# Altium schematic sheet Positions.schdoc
size 368 x 210 mm
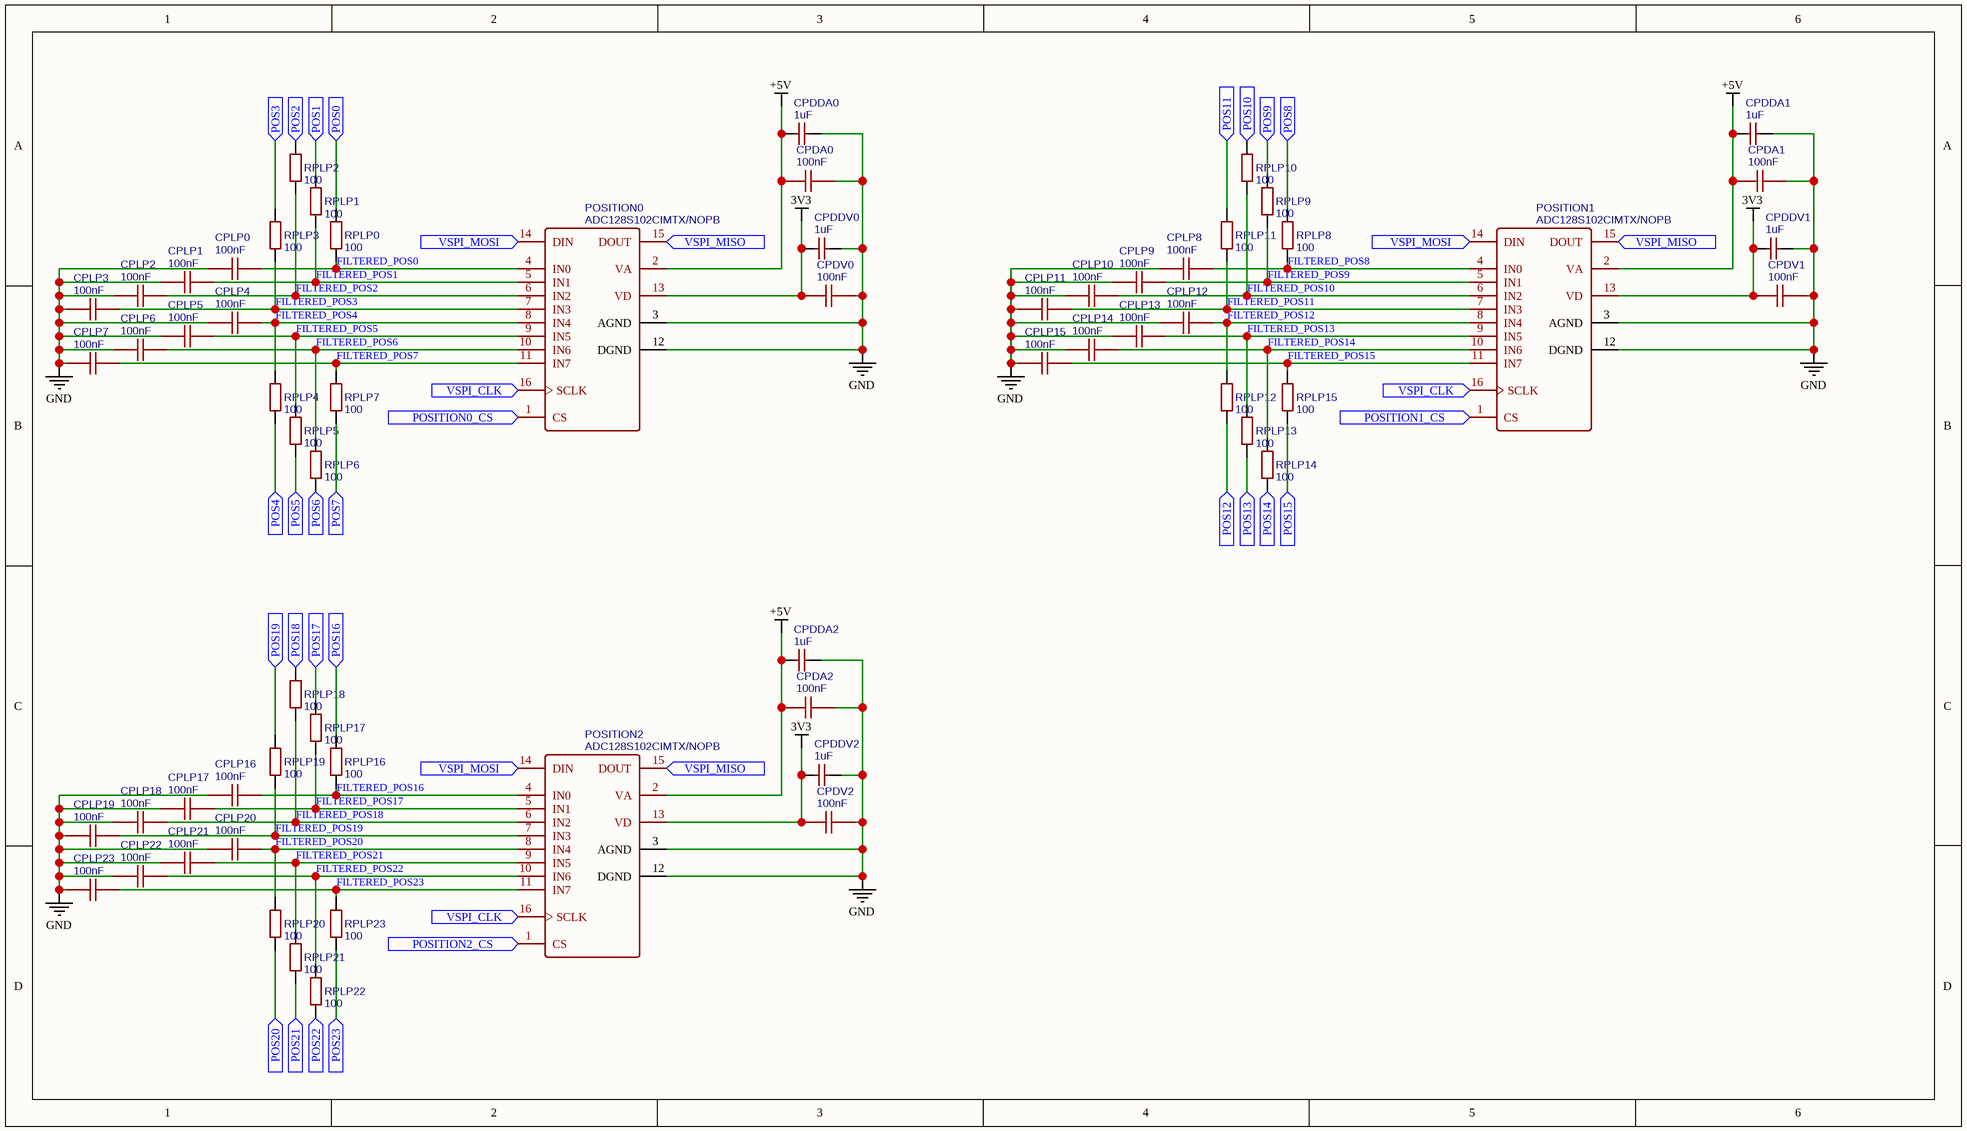
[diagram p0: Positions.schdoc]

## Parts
CPDA0  100nF  [0603]
CPDA1  100nF  [0603]
CPDA2  100nF  [0603]
CPDDA0  1uF  [0603]
CPDDA1  1uF  [0603]
CPDDA2  1uF  [0603]
CPDDV0  1uF  [0603]
CPDDV1  1uF  [0603]
CPDDV2  1uF  [0603]
CPDV0  100nF  [0603]
CPDV1  100nF  [0603]
CPDV2  100nF  [0603]
CPLP0  100nF  [0603]
CPLP1  100nF  [0603]
CPLP2  100nF  [0603]
CPLP3  100nF  [0603]
CPLP4  100nF  [0603]
CPLP5  100nF  [0603]
CPLP6  100nF  [0603]
CPLP7  100nF  [0603]
CPLP8  100nF  [0603]
CPLP9  100nF  [0603]
CPLP10  100nF  [0603]
CPLP11  100nF  [0603]
CPLP12  100nF  [0603]
CPLP13  100nF  [0603]
CPLP14  100nF  [0603]
CPLP15  100nF  [0603]
CPLP16  100nF  [0603]
CPLP17  100nF  [0603]
CPLP18  100nF  [0603]
CPLP19  100nF  [0603]
CPLP20  100nF  [0603]
CPLP21  100nF  [0603]
CPLP22  100nF  [0603]
CPLP23  100nF  [0603]
POSITION0  ADC128S102CIMTX/NOPB  [TSSOP-16-DOT-BOTTOM-RIGHT]
POSITION1  ADC128S102CIMTX/NOPB  [TSSOP-16-DOT-BOTTOM-RIGHT]
POSITION2  ADC128S102CIMTX/NOPB  [TSSOP-16-DOT-BOTTOM-RIGHT]
RPLP0  100  [0603]
RPLP1  100  [0603]
RPLP2  100  [0603]
RPLP3  100  [0603]
RPLP4  100  [0603]
RPLP5  100  [0603]
RPLP6  100  [0603]
RPLP7  100  [0603]
RPLP8  100  [0603]
RPLP9  100  [0603]
RPLP10  100  [0603]
RPLP11  100  [0603]
RPLP12  100  [0603]
RPLP13  100  [0603]
RPLP14  100  [0603]
RPLP15  100  [0603]
RPLP16  100  [0603]
RPLP17  100  [0603]
RPLP18  100  [0603]
RPLP19  100  [0603]
RPLP20  100  [0603]
RPLP21  100  [0603]
RPLP22  100  [0603]
RPLP23  100  [0603]

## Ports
POS0, POS1, POS2, POS3, POS4, POS5, POS6, POS7, POS8, POS9, POS10, POS11, POS12, POS13, POS14, POS15, POS16, POS17, POS18, POS19, POS20, POS21, POS22, POS23, POSITION0_CS, POSITION1_CS, POSITION2_CS, VSPI_CLK, VSPI_MISO, VSPI_MOSI

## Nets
3V3: CPDDV0.1 CPDDV1.1 CPDDV2.1 CPDV0.1 CPDV1.1 CPDV2.1 POSITION0.13(VD) POSITION1.13(VD) POSITION2.13(VD)
+5V: CPDA0.1 CPDA1.1 CPDA2.1 CPDDA0.1 CPDDA1.1 CPDDA2.1 POSITION0.2(VA) POSITION1.2(VA) POSITION2.2(VA)
GND: CPDA0.2 CPDA1.2 CPDA2.2 CPDDA0.2 CPDDA1.2 CPDDA2.2 CPDDV0.2 CPDDV1.2 CPDDV2.2 CPDV0.2 CPDV1.2 CPDV2.2 CPLP0.2 CPLP1.2 CPLP2.2 CPLP3.2 CPLP4.2 CPLP5.2 CPLP6.2 CPLP7.2 CPLP8.2 CPLP9.2 CPLP10.2 CPLP11.2 CPLP12.2 CPLP13.2 CPLP14.2 CPLP15.2 CPLP16.2 CPLP17.2 CPLP18.2 CPLP19.2 CPLP20.2 CPLP21.2 CPLP22.2 CPLP23.2 POSITION0.3(AGND) POSITION0.12(DGND) POSITION1.3(AGND) POSITION1.12(DGND) POSITION2.3(AGND) POSITION2.12(DGND)
FILTERED_POS0: CPLP0.1 POSITION0.4(IN0) RPLP0.1
FILTERED_POS1: CPLP1.1 POSITION0.5(IN1) RPLP1.1
FILTERED_POS2: CPLP2.1 POSITION0.6(IN2) RPLP2.1
FILTERED_POS3: CPLP3.1 POSITION0.7(IN3) RPLP3.1
FILTERED_POS4: CPLP4.1 POSITION0.8(IN4) RPLP4.2
FILTERED_POS5: CPLP5.1 POSITION0.9(IN5) RPLP5.2
FILTERED_POS6: CPLP6.1 POSITION0.10(IN6) RPLP6.2
FILTERED_POS7: CPLP7.1 POSITION0.11(IN7) RPLP7.2
FILTERED_POS8: CPLP8.1 POSITION1.4(IN0) RPLP8.1
FILTERED_POS9: CPLP9.1 POSITION1.5(IN1) RPLP9.1
FILTERED_POS10: CPLP10.1 POSITION1.6(IN2) RPLP10.1
FILTERED_POS11: CPLP11.1 POSITION1.7(IN3) RPLP11.1
FILTERED_POS12: CPLP12.1 POSITION1.8(IN4) RPLP12.2
FILTERED_POS13: CPLP13.1 POSITION1.9(IN5) RPLP13.2
FILTERED_POS14: CPLP14.1 POSITION1.10(IN6) RPLP14.2
FILTERED_POS15: CPLP15.1 POSITION1.11(IN7) RPLP15.2
FILTERED_POS16: CPLP16.1 POSITION2.4(IN0) RPLP16.1
FILTERED_POS17: CPLP17.1 POSITION2.5(IN1) RPLP17.1
FILTERED_POS18: CPLP18.1 POSITION2.6(IN2) RPLP18.1
FILTERED_POS19: CPLP19.1 POSITION2.7(IN3) RPLP19.1
FILTERED_POS20: CPLP20.1 POSITION2.8(IN4) RPLP20.2
FILTERED_POS21: CPLP21.1 POSITION2.9(IN5) RPLP21.2
FILTERED_POS22: CPLP22.1 POSITION2.10(IN6) RPLP22.2
FILTERED_POS23: CPLP23.1 POSITION2.11(IN7) RPLP23.2
POS0: RPLP0.2 ; port POS0
POS1: RPLP1.2 ; port POS1
POS2: RPLP2.2 ; port POS2
POS3: RPLP3.2 ; port POS3
POS4: RPLP4.1 ; port POS4
POS5: RPLP5.1 ; port POS5
POS6: RPLP6.1 ; port POS6
POS7: RPLP7.1 ; port POS7
POS8: RPLP8.2 ; port POS8
POS9: RPLP9.2 ; port POS9
POS10: RPLP10.2 ; port POS10
POS11: RPLP11.2 ; port POS11
POS12: RPLP12.1 ; port POS12
POS13: RPLP13.1 ; port POS13
POS14: RPLP14.1 ; port POS14
POS15: RPLP15.1 ; port POS15
POS16: RPLP16.2 ; port POS16
POS17: RPLP17.2 ; port POS17
POS18: RPLP18.2 ; port POS18
POS19: RPLP19.2 ; port POS19
POS20: RPLP20.1 ; port POS20
POS21: RPLP21.1 ; port POS21
POS22: RPLP22.1 ; port POS22
POS23: RPLP23.1 ; port POS23
POSITION0_CS: POSITION0.1(CS) ; port POSITION0_CS
POSITION1_CS: POSITION1.1(CS) ; port POSITION1_CS
POSITION2_CS: POSITION2.1(CS) ; port POSITION2_CS
VSPI_CLK: POSITION0.16(SCLK) POSITION1.16(SCLK) POSITION2.16(SCLK) ; port VSPI_CLK
VSPI_MISO: POSITION0.15(DOUT) POSITION1.15(DOUT) POSITION2.15(DOUT) ; port VSPI_MISO
VSPI_MOSI: POSITION0.14(DIN) POSITION1.14(DIN) POSITION2.14(DIN) ; port VSPI_MOSI

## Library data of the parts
CPDA0-CPDA2 CPDV0-CPDV2 CPLP0-CPLP23 = 100nF: BOM_Manufacturer: YAGEO; BOM_Manufacturer Part: CC0603KRX7R9BB104; nameAlias: Capacitance; SMT Type: Basic
CPDDA0-CPDDA2 CPDDV0-CPDDV2 = 1uF: BOM_Manufacturer Part: CL10A105KB8NNNC; BOM_Manufacturer: SAMSUNG; nameAlias: Capacitance; SMT Type: Basic
POSITION0-POSITION2 = ADC128S102CIMTX/NOPB: BOM_Manufacturer: TI; Contributor: LCSC; SMT Type: Extend
RPLP0-RPLP23 = 100: BOM_Manufacturer: UniOhm; BOM_Manufacturer Part: 0603WAF1000T5E; nameAlias: Resistance (Ohms); SMT Type: Basic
